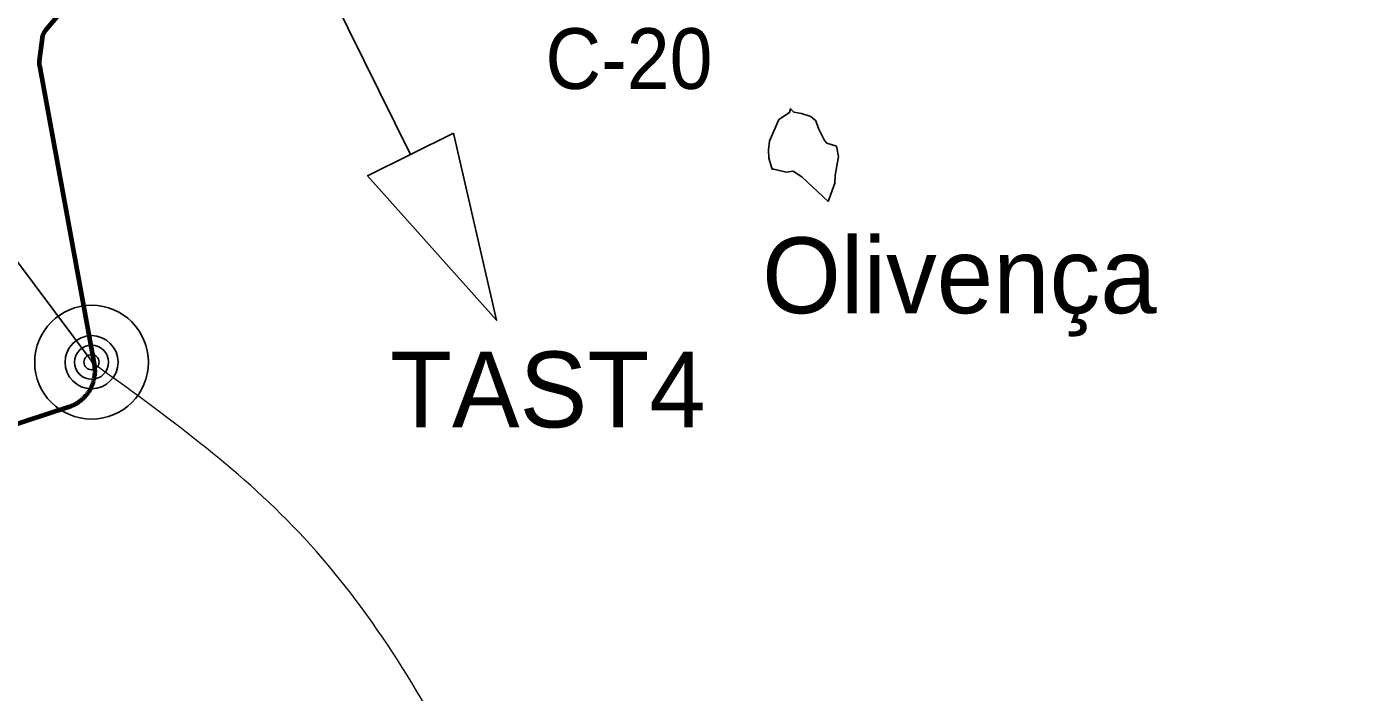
# Model space of a CAD drawing. Extents: x -1643653 to 4543381, y 1624270 to 13878484.
# Drawn here: x 693536 to 702315, y 8943797 to 8948185 of the extents above; entities that cross this region are included whole.
import ezdxf
from ezdxf.enums import TextEntityAlignment as Align

# ---------------------------------------------------------------- set-up
doc = ezdxf.new("R2010")
doc.units = 0
doc.header["$LTSCALE"] = 160
for name, color, linetype, lineweight in [('15', 7, 'Continuous', 25), ('21', 7, 'Continuous', 25), ('50', 7, 'Continuous', 13), ('54', 7, 'Continuous', 25), ('60', 7, 'Continuous', 13), ('61', 7, 'Continuous', 70)]:
    doc.layers.add(name, color=color, linetype=linetype, lineweight=lineweight)
doc.layers.add('41', color=7, linetype='Continuous')

msp = doc.modelspace()

# ---------------------------------------------------------------- linework, layer by layer
at = {"layer": '15'}
for radius in [375, 175, 112.5, 50]:
    msp.add_circle((693963.6, 8945973), radius, dxfattribs=at)
at = {"layer": '21'}
for points in [[(698875, 8947397.9), (698811.7, 8947415.6), (698794.2, 8947433.6), (698754.7, 8947514.3), (698737.5, 8947564.1), (698706.2, 8947592.7), (698643, 8947613), (698593.3, 8947619.9), (698571.6, 8947643.2), (698565.2, 8947619.3), (698494.7, 8947572.1), (698431.7, 8947429.7), (698426.6, 8947373.4), (698428.3, 8947318.5), (698449.3, 8947244.8)], [(698819.7, 8947032.6), (698863.9, 8947152.1), (698866.6, 8947202.8), (698888.3, 8947328.1), (698875, 8947397.9)], [(698449.3, 8947244.8), (698461.1, 8947244.4), (698543.5, 8947225.9), (698588, 8947231.3), (698646.7, 8947194.3), (698819.7, 8947032.6)]]:
    msp.add_lwpolyline(points, dxfattribs=at)
at = {"layer": '50'}
msp.add_spline([(696981.7, 8940219.8), (696981.7, 8941765), (696402.6, 8943282.7), (695327.1, 8944855.5), (693963.6, 8945973)], degree=3, dxfattribs=at)
at = {"layer": '54'}
for p, q in [((695519.6, 8948445.1), (696066.6, 8947342.2)), ((693967.1, 8945976.3), (693229.8, 8946962.2))]:
    msp.add_line(p, q, dxfattribs=at)
msp.add_lwpolyline([(696349.5, 8947482.5), (696633.6, 8946249.2), (695783.7, 8947201.9)], close=True, dxfattribs=at)
at = {"layer": '60', "lineweight": 25}
msp.add_spline([(814781, 9009175.5), (814787.2, 9009173.4), (814796.9, 9009173.4), (814799.4, 9009172.4), (814805.1, 9009174.5), (814805.6, 9009176.5), (814811.7, 9009179.5), (814811.7, 9009179.5), (814801.5, 9009181), (814790.7, 9009181.5), (814784.1, 9009183.1), (814777.4, 9009185.1), (814778.4, 9009175.5)], degree=3, dxfattribs=at)
at = {"layer": '61'}
for points in [[(693888, 8948432.1), (693660, 8948159.8), (693658.2, 8948157.6), (693656.4, 8948155.3), (693654.8, 8948153.1), (693653.2, 8948150.7), (693651.7, 8948148.3), (693650.2, 8948145.9), (693648.8, 8948143.5), (693647.5, 8948141), (693646.2, 8948138.4), (693645.1, 8948135.8), (693644, 8948133.2), (693642.9, 8948130.6), (693642, 8948127.9), (693641.1, 8948125.2), (693640.3, 8948122.5), (693639.6, 8948119.8), (693638.9, 8948117.1), (693638.4, 8948114.3), (693637.9, 8948111.5), (693637.5, 8948108.7), (693637.4, 8948108), (693618.8, 8947958.9), (693618.4, 8947956.1), (693618.2, 8947953.2), (693618.1, 8947950.4), (693618, 8947947.6), (693618, 8947944.8), (693618.1, 8947942), (693618.2, 8947939.1), (693618.5, 8947936.3), (693618.8, 8947933.5), (693619.2, 8947930.7), (693619.6, 8947928.5), (693980.2, 8945959.2), (693980.9, 8945954.8), (693981.6, 8945950.3), (693982.2, 8945945.9), (693982.8, 8945941.5), (693983.2, 8945937), (693983.6, 8945932.6), (693983.8, 8945928.1), (693984.1, 8945923.6), (693984.2, 8945919.2), (693984.2, 8945914.7), (693984.2, 8945910.2), (693984.1, 8945905.8), (693983.9, 8945901.3), (693983.6, 8945896.8), (693983.3, 8945892.4), (693982.9, 8945887.9), (693982.3, 8945883.5), (693981.8, 8945879), (693981.1, 8945874.6), (693980.3, 8945870.2), (693979.5, 8945865.8), (693978.6, 8945861.4), (693977.6, 8945857.1), (693976.6, 8945852.7), (693975.4, 8945848.4), (693974.2, 8945844.1), (693972.9, 8945839.8), (693971.6, 8945835.6), (693970.1, 8945831.3), (693968.6, 8945827.1), (693967, 8945822.9), (693965.3, 8945818.8), (693963.6, 8945814.7), (693961.8, 8945810.6), (693959.9, 8945806.5), (693957.9, 8945802.5), (693955.9, 8945798.5), (693953.8, 8945794.6), (693951.6, 8945790.7), (693949.4, 8945786.8), (693947.1, 8945783), (693944.7, 8945779.2), (693942.2, 8945775.4), (693939.7, 8945771.8), (693937.1, 8945768.1), (693934.5, 8945764.5), (693931.8, 8945760.9), (693929, 8945757.4), (693926.2, 8945754), (693923.3, 8945750.6), (693920.3, 8945747.2), (693917.3, 8945743.9)], [(693917.3, 8945743.9), (693914.2, 8945740.7), (693911.1, 8945737.5), (693907.9, 8945734.3), (693904.7, 8945731.2), (693901.4, 8945728.2), (693898, 8945725.3), (693894.6, 8945722.4), (693891.2, 8945719.5), (693887.7, 8945716.8), (693884.1, 8945714), (693880.5, 8945711.4), (693876.8, 8945708.8), (693873.2, 8945706.3), (693869.4, 8945703.8), (693865.6, 8945701.4), (693861.8, 8945699.1), (693857.9, 8945696.9), (693854, 8945694.7), (693850.1, 8945692.6), (693846.1, 8945690.6), (693842.1, 8945688.6), (693838, 8945686.7), (693834, 8945684.9), (693829.8, 8945683.1), (693825.7, 8945681.5), (693821.5, 8945679.9), (693817.3, 8945678.3), (693813.1, 8945676.9), (693811.7, 8945676.5), (693388.8, 8945538.6)]]:
    msp.add_lwpolyline(points, dxfattribs=at)

# ---------------------------------------------------------------- texts
at = {"layer": '15', "width": 0.95}
msp.add_text('C-20', height=400, dxfattribs=at).set_placement((696955.6, 8947774.1))
at = {"layer": '41'}
msp.add_text('Olivença', height=500, dxfattribs=at).set_placement((698383.7, 8946295.8))
at = {"layer": '54'}
msp.add_text('TAST4', height=500, dxfattribs=at).set_placement((696971.1, 8945543.5), align=Align.CENTER)

doc.saveas('drawing.dxf')
